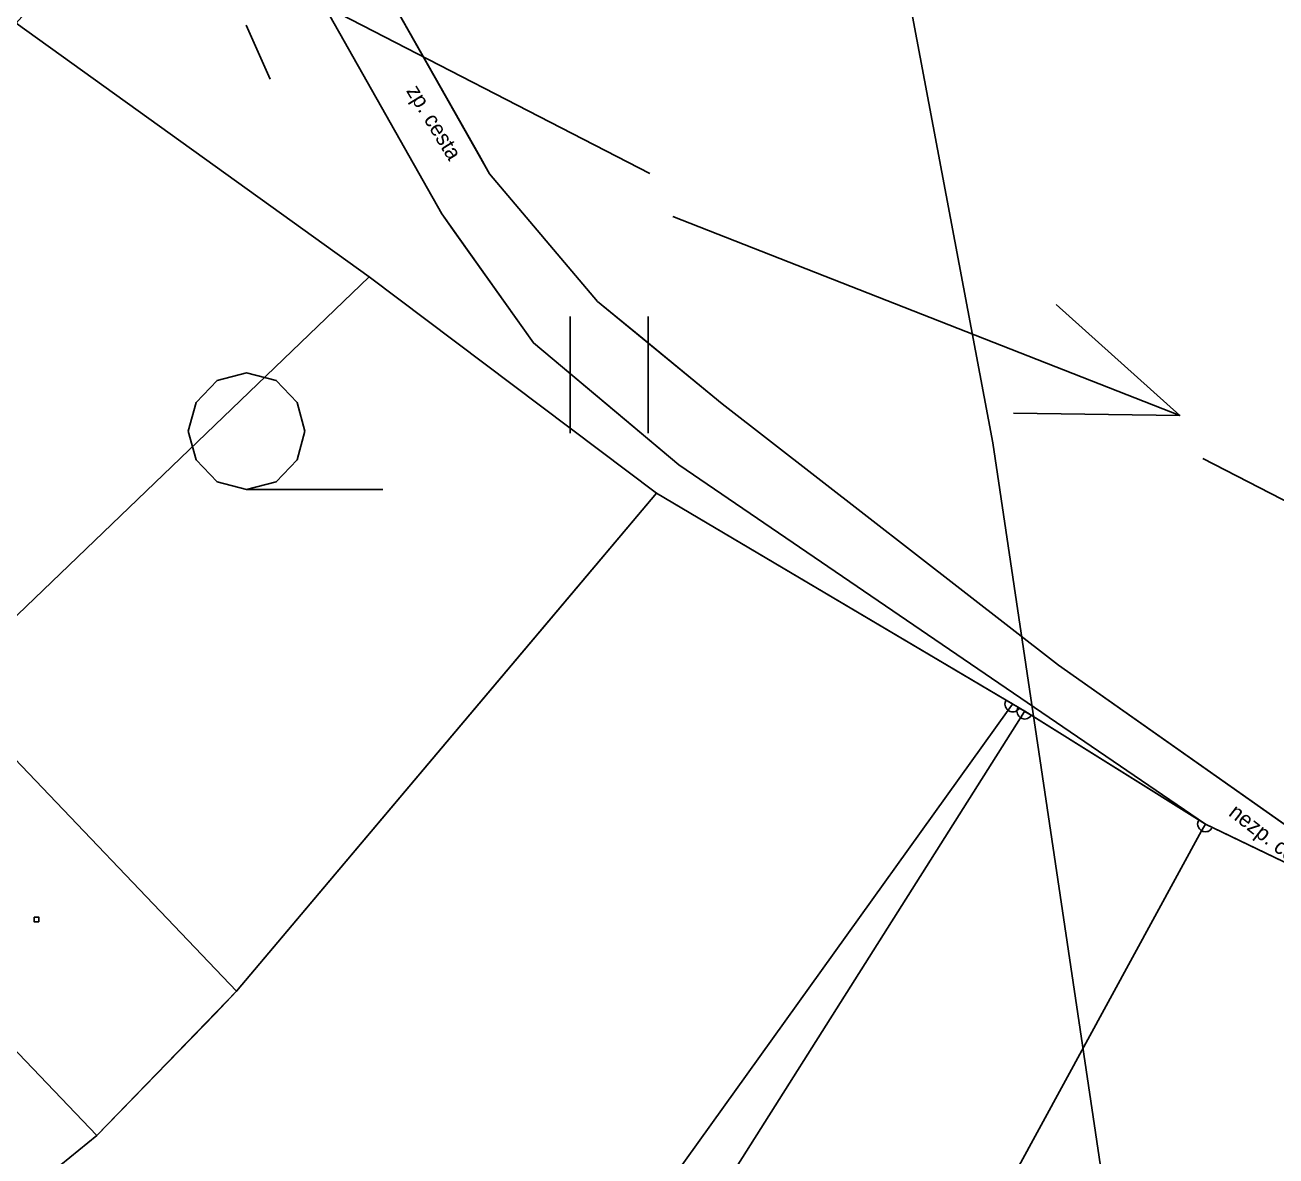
# Model space of a CAD drawing. Extents: x -645676 to -642474, y -1077513 to -1072613.
# Drawn here: x -644274.2 to -644193.8, y -1074412.5 to -1074339.8 of the extents above; entities that cross this region are included whole.
import ezdxf

# ---------------------------------------------------------------- set-up
doc = ezdxf.new("R2010")
doc.units = 0
for name, color, linetype in [('KN', 7, 'Continuous'), ('KULTURY_STAV', 7, 'Continuous'), ('KULTURY_ZNACKY', 7, 'Continuous'), ('M_stn__komunikace', 7, 'Continuous'), ('Obvod_KP_', 7, 'Continuous'), ('OBVOD_PU', 7, 'Continuous'), ('VODOVOD', 7, 'Continuous'), ('VRSTEVNICE', 7, 'Continuous')]:
    doc.layers.add(name, color=color, linetype=linetype)

# ---------------------------------------------------------------- blocks, each defined once
blk = doc.blocks.new('3$0400')
blk.add_lwpolyline([(0, 0), (-0.38, 0.1), (-0.65, 0.38), (-0.75, 0.75), (-0.65, 1.12), (-0.38, 1.4), (0, 1.5), (0.38, 1.4), (0.65, 1.12), (0.75, 0.75), (0.65, 0.38), (0.38, 0.1), (0, 0), (1.75, 0)])
blk = doc.blocks.new('3$0600')
for p, q in [((-0.5, 1.5), (-0.5, 0)), ((0.5, 0), (0.5, 1.5))]:
    blk.add_line(p, q)
blk = doc.blocks.new('6$1520')
blk.add_line((-3.5, 0), (3.5, 0))
blk.add_lwpolyline([(1.5, 0.75), (3.5, 0), (1.5, -0.75)])

msp = doc.modelspace()

# ---------------------------------------------------------------- linework, layer by layer
at = {"layer": 'KN'}
for points in [[(-644252.04, -1074355.97), (-644276.87, -1074379.81), (-644277.07, -1074384.61), (-644286.4, -1074393.52), (-644289.36, -1074396.35), (-644296.37, -1074403.05), (-644301.67, -1074397.75), (-644282.28, -1074363.06), (-644290.24, -1074355.04), (-644274.73, -1074339.66)], [(-644233.57, -1074369.87), (-644260.56, -1074401.89), (-644277.07, -1074384.61), (-644276.87, -1074379.81), (-644252.04, -1074355.97)], [(-644210.69, -1074383.42), (-644210.69, -1074383.43), (-644210.69, -1074383.44), (-644210.97, -1074383.83), (-644211, -1074383.81), (-644211.06, -1074383.75), (-644211.11, -1074383.68), (-644211.15, -1074383.6), (-644211.17, -1074383.52), (-644211.18, -1074383.43), (-644211.17, -1074383.34), (-644211.15, -1074383.26), (-644211.11, -1074383.18)], [(-644210.34, -1074383.63), (-644210.34, -1074383.64), (-644210.38, -1074383.72), (-644210.4, -1074383.8), (-644210.41, -1074383.85), (-644210.43, -1074383.86), (-644210.51, -1074383.9), (-644210.59, -1074383.92), (-644210.68, -1074383.93), (-644210.77, -1074383.92), (-644210.85, -1074383.9), (-644210.93, -1074383.86), (-644210.97, -1074383.83), (-644210.69, -1074383.44), (-644210.68, -1074383.44), (-644210.67, -1074383.44)], [(-644210.68, -1074383.43), (-644210.69, -1074383.44), (-644210.69, -1074383.43), (-644210.69, -1074383.42)], [(-644210.67, -1074383.44), (-644210.68, -1074383.44), (-644210.69, -1074383.44), (-644210.68, -1074383.43)], [(-644210.41, -1074383.85), (-644210.41, -1074383.89), (-644210.4, -1074383.98), (-644210.38, -1074384.06), (-644210.34, -1074384.14), (-644210.29, -1074384.21), (-644210.23, -1074384.27), (-644210.18, -1074384.31), (-644238.43, -1074429.01), (-644239.25, -1074428.43), (-644241.27, -1074426.08), (-644210.97, -1074383.83), (-644210.93, -1074383.86), (-644210.85, -1074383.9), (-644210.77, -1074383.92), (-644210.68, -1074383.93), (-644210.59, -1074383.92), (-644210.51, -1074383.9), (-644210.43, -1074383.86)], [(-644210.25, -1074383.69), (-644210.3, -1074383.75), (-644210.36, -1074383.81), (-644210.41, -1074383.85), (-644210.4, -1074383.8), (-644210.38, -1074383.72), (-644210.34, -1074383.64), (-644210.34, -1074383.63)], [(-644209.92, -1074383.88), (-644209.92, -1074383.89), (-644209.92, -1074383.9), (-644210.18, -1074384.31), (-644210.23, -1074384.27), (-644210.29, -1074384.21), (-644210.34, -1074384.14), (-644210.38, -1074384.06), (-644210.4, -1074383.98), (-644210.41, -1074383.89), (-644210.41, -1074383.85), (-644210.36, -1074383.81), (-644210.3, -1074383.75), (-644210.25, -1074383.69)], [(-644209.49, -1074384.15), (-644209.53, -1074384.21), (-644209.59, -1074384.27), (-644209.66, -1074384.32), (-644209.74, -1074384.36), (-644209.82, -1074384.38), (-644209.91, -1074384.39), (-644210, -1074384.38), (-644210.08, -1074384.36), (-644210.16, -1074384.32), (-644210.18, -1074384.31), (-644209.92, -1074383.9), (-644209.91, -1074383.9), (-644209.9, -1074383.9)], [(-644209.91, -1074383.89), (-644209.92, -1074383.9), (-644209.92, -1074383.89), (-644209.92, -1074383.88)], [(-644209.9, -1074383.9), (-644209.91, -1074383.9), (-644209.92, -1074383.9), (-644209.91, -1074383.89)], [(-644260.56, -1074401.89), (-644269.55, -1074411.17), (-644280.98, -1074399.2), (-644286.4, -1074393.52), (-644277.07, -1074384.61)], [(-644198.31, -1074391.13), (-644198.31, -1074391.14), (-644198.31, -1074391.15), (-644198.3, -1074391.15), (-644198.54, -1074391.58), (-644198.55, -1074391.57), (-644198.62, -1074391.52), (-644198.68, -1074391.46), (-644198.73, -1074391.39), (-644198.77, -1074391.31), (-644198.79, -1074391.23), (-644198.8, -1074391.14), (-644198.79, -1074391.05), (-644198.77, -1074390.97), (-644198.73, -1074390.89), (-644198.72, -1074390.88)], [(-644197.85, -1074391.36), (-644197.87, -1074391.39), (-644197.92, -1074391.46), (-644197.98, -1074391.52), (-644198.05, -1074391.57), (-644198.13, -1074391.61), (-644198.21, -1074391.63), (-644198.3, -1074391.64), (-644198.39, -1074391.63), (-644198.47, -1074391.61), (-644198.54, -1074391.58), (-644198.3, -1074391.15), (-644198.29, -1074391.15), (-644198.29, -1074391.14)], [(-644198.3, -1074391.14), (-644198.3, -1074391.15), (-644198.31, -1074391.15), (-644198.31, -1074391.14), (-644198.31, -1074391.13)], [(-644198.29, -1074391.14), (-644198.29, -1074391.15), (-644198.3, -1074391.15), (-644198.3, -1074391.14)], [(-644273.27, -1074397.43), (-644273.57, -1074397.43), (-644273.57, -1074397.13), (-644273.27, -1074397.13)], [(-644273.27, -1074397.43), (-644273.27, -1074397.13), (-644273.57, -1074397.13), (-644273.57, -1074397.43)]]:
    msp.add_lwpolyline(points, close=True, dxfattribs=at)
for points in [[(-644273.59, -1074414.45), (-644269.55, -1074411.17), (-644260.56, -1074401.89), (-644233.57, -1074369.87), (-644211.11, -1074383.18), (-644211.15, -1074383.26), (-644211.17, -1074383.34), (-644211.18, -1074383.43), (-644211.17, -1074383.52), (-644211.15, -1074383.6), (-644211.11, -1074383.68), (-644211.06, -1074383.75), (-644211, -1074383.81), (-644210.97, -1074383.83), (-644241.27, -1074426.08)], [(-644238.43, -1074429.01), (-644210.18, -1074384.31), (-644210.16, -1074384.32), (-644210.08, -1074384.36), (-644210, -1074384.38), (-644209.91, -1074384.39), (-644209.82, -1074384.38), (-644209.74, -1074384.36), (-644209.66, -1074384.32), (-644209.59, -1074384.27), (-644209.53, -1074384.21), (-644209.49, -1074384.15), (-644198.72, -1074390.88), (-644198.73, -1074390.89), (-644198.77, -1074390.97), (-644198.79, -1074391.05), (-644198.8, -1074391.14), (-644198.79, -1074391.23), (-644198.77, -1074391.31), (-644198.73, -1074391.39), (-644198.68, -1074391.46), (-644198.62, -1074391.52), (-644198.55, -1074391.57), (-644198.54, -1074391.58), (-644222.28, -1074435.16)], [(-644222.28, -1074435.16), (-644198.54, -1074391.58), (-644198.47, -1074391.61), (-644198.39, -1074391.63), (-644198.3, -1074391.64), (-644198.21, -1074391.63), (-644198.13, -1074391.61), (-644198.05, -1074391.57), (-644197.98, -1074391.52), (-644197.92, -1074391.46), (-644197.87, -1074391.39), (-644197.85, -1074391.36), (-644160.16, -1074409.49)], [(-644280.98, -1074399.2), (-644269.55, -1074411.17), (-644273.59, -1074414.45), (-644286.55, -1074424.98)]]:
    msp.add_lwpolyline(points, dxfattribs=at)
at = {"layer": 'KULTURY_STAV'}
for points in [[(-644126.83, -1074482.96), (-644165.01, -1074461.76), (-644166.37, -1074461.12), (-644170.07, -1074467.93), (-644188.71, -1074458.4), (-644160.16, -1074409.49), (-644182.34, -1074398.82), (-644207.74, -1074380.94), (-644229.36, -1074364.14), (-644237.36, -1074357.56), (-644244.3, -1074349.35), (-644252.39, -1074335.07), (-644259.71, -1074321.97), (-644260.16, -1074320.59), (-644260.26, -1074320.28), (-644253.72, -1074304.8), (-644245.38, -1074286.12), (-644237.75, -1074263.02), (-644232.1, -1074235.01), (-644225.62, -1074205.16), (-644220.96, -1074188.13), (-644213.58, -1074171.03), (-644204.81, -1074155.89), (-644196.84, -1074144.68)], [(-644237.75, -1074263.02), (-644245.38, -1074286.12), (-644253.72, -1074304.8), (-644260.26, -1074320.28), (-644260.16, -1074320.59), (-644259.71, -1074321.97), (-644254.97, -1074330.45), (-644252.39, -1074335.07), (-644244.97, -1074348.16), (-644244.3, -1074349.35), (-644237.36, -1074357.56), (-644234.7, -1074359.75), (-644229.36, -1074364.14), (-644207.74, -1074380.94), (-644182.35, -1074398.82)], [(-644265.03, -1074328.55), (-644265.01, -1074328.56), (-644262.88, -1074329.45), (-644258.81, -1074332.51), (-644255.76, -1074337.05), (-644247.38, -1074351.92), (-644241.49, -1074360.22), (-644232.14, -1074368.05), (-644198.3, -1074391.14), (-644209.91, -1074383.89), (-644210.68, -1074383.43), (-644233.57, -1074369.87), (-644252.04, -1074355.97), (-644274.73, -1074339.66), (-644265.46, -1074329.3), (-644265.03, -1074328.55)], [(-644273.59, -1074414.45), (-644269.55, -1074411.17), (-644261.95, -1074403.33), (-644260.56, -1074401.89), (-644240, -1074377.5), (-644233.57, -1074369.87), (-644210.68, -1074383.43), (-644209.91, -1074383.89), (-644198.3, -1074391.14), (-644232.14, -1074368.05), (-644236.17, -1074364.67), (-644241.49, -1074360.22), (-644246.51, -1074353.15), (-644247.38, -1074351.92), (-644255.76, -1074337.05)], [(-644274.73, -1074339.66), (-644252.04, -1074355.97), (-644233.57, -1074369.87), (-644260.56, -1074401.89), (-644277.07, -1074384.61), (-644286.4, -1074393.52), (-644289.36, -1074396.35), (-644296.37, -1074403.05), (-644301.67, -1074397.75), (-644282.28, -1074363.06), (-644290.24, -1074355.04), (-644274.73, -1074339.66)], [(-644277.07, -1074384.61), (-644260.56, -1074401.89), (-644269.55, -1074411.17), (-644273.59, -1074414.45), (-644262.75, -1074424.22), (-644255.08, -1074431.13), (-644262.02, -1074436.88), (-644268.73, -1074442.44), (-644267.84, -1074443.78), (-644266.9, -1074445.14), (-644255.49, -1074461.66), (-644254.52, -1074462.97), (-644263.4, -1074469.02), (-644261.46, -1074477.01)]]:
    msp.add_lwpolyline(points, dxfattribs=at)
at = {"layer": 'Obvod_KP_'}
msp.add_lwpolyline([(-644348.3, -1074277.02), (-644328.48, -1074294.08), (-644281.65, -1074330.81), (-644274.73, -1074339.66), (-644252.04, -1074355.97), (-644233.57, -1074369.87), (-644210.68, -1074383.43), (-644209.91, -1074383.89), (-644198.3, -1074391.14), (-644160.16, -1074409.49), (-644144.46, -1074417.05), (-644148.65, -1074428.45), (-644170.07, -1074467.93), (-644145.13, -1074484.54)], dxfattribs=at)
at = {"layer": 'OBVOD_PU'}
for points in [[(-644145.13, -1074484.54), (-644170.07, -1074467.93), (-644148.65, -1074428.45), (-644144.46, -1074417.05), (-644160.16, -1074409.49), (-644198.3, -1074391.14), (-644209.91, -1074383.89), (-644210.68, -1074383.43), (-644233.57, -1074369.87), (-644252.04, -1074355.97), (-644274.73, -1074339.66), (-644281.65, -1074330.81), (-644272.76, -1074316.93), (-644263.01, -1074299.24), (-644257.6, -1074284.78), (-644247.58, -1074254.38), (-644241.28, -1074223.42), (-644237.07, -1074200.98), (-644232.18, -1074182.35), (-644227.01, -1074170.18), (-644210.92, -1074143.77)], [(-644348.3, -1074277.02), (-644328.48, -1074294.08), (-644281.65, -1074330.81), (-644274.73, -1074339.66), (-644252.04, -1074355.97), (-644233.57, -1074369.87), (-644210.68, -1074383.43), (-644209.91, -1074383.89), (-644198.3, -1074391.14), (-644160.16, -1074409.49), (-644144.46, -1074417.05), (-644148.65, -1074428.45), (-644170.07, -1074467.93), (-644145.13, -1074484.54)]]:
    msp.add_lwpolyline(points, dxfattribs=at)
at = {"layer": 'VODOVOD'}
for p, q in [((-644260.68, -1074335.58), (-644234.01, -1074349.32)), ((-644259.94, -1074339.8), (-644258.4, -1074343.26)), ((-644198.46, -1074367.65), (-644144.77, -1074395.32))]:
    msp.add_line(p, q, dxfattribs=at)
at = {"layer": 'VRSTEVNICE'}
msp.add_lwpolyline([(-644182.06, -1074479.14), (-644188.62, -1074467.75), (-644192.89, -1074458.63), (-644198.73, -1074442.4), (-644204, -1074420.18), (-644211.97, -1074366.63), (-644218.24, -1074333.3), (-644224.79, -1074303.39), (-644230.06, -1074289.43), (-644238.18, -1074275.48), (-644244.3, -1074267.93), (-644250, -1074262.23), (-644260.97, -1074253.54), (-644279.2, -1074243.57), (-644294.58, -1074237.02), (-644337.3, -1074224.49), (-644371.48, -1074217.37), (-644388.58, -1074212.95), (-644409.65, -1074205.41), (-644433.87, -1074193.44)], dxfattribs=at)

# ---------------------------------------------------------------- block references
at = {"layer": 'KULTURY_ZNACKY', "xscale": 5, "yscale": 5}
for name, p in [('3$0600', (-644236.62, -1074366.02)), ('3$0400', (-644259.92, -1074369.64))]:
    msp.add_blockref(name, p, dxfattribs=at)
at = {"layer": 'VODOVOD', "xscale": 5.000000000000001, "yscale": 5, "rotation": -21.459275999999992}
msp.add_blockref('6$1520', (-644216.24, -1074358.49), dxfattribs=at)

# ---------------------------------------------------------------- texts
at = {"layer": 'M_stn__komunikace'}
for s, rotation, p in [('zp. cesta', 301.501, (-644249.69, -1074344.01)), ('nezp. cesta', 322.185, (-644196.87, -1074390.55))]:
    msp.add_text(s, height=1, rotation=rotation, dxfattribs=at).set_placement(p)

doc.saveas('drawing.dxf')
